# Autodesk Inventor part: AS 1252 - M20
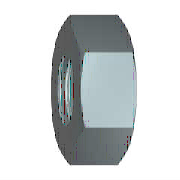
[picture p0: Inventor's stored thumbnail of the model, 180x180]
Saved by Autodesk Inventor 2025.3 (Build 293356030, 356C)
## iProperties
IsCustomPart: 0
Created: 2024-01
Part Number: AS 1252 - M20
Material: Acero, suave
Description: Pernos de acero Perno hex
Document SubType Name: Modeling
Standard: AS 1252
Designer: User
Standards Organization: AS
Language: es-ES
Size Designation: M20
Categories: <MemberInstance><Categories><Category DisplayName="Fijaciones" InternalName="e4da775c-781d-43d5-af7c-5136215cf5a6" Mnemonic="FSTN"><Category DisplayName="Tuerca
Density: 7.85 g/cm^3
Appearance: Semipulido
Author: User
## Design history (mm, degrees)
workaxis "Work Axis1"
workplane "Work Plane1"
sketch "Boceto1"
  geometry: L1 (-18.475, 0)-(-9.238, 16); L2 (-9.238, 16)-(9.238, 16); L3 (9.238, 16)-(18.475, 0); L4 (18.475, 0)-(9.238, -16); L5 (9.238, -16)-(-9.238, -16); L6 (-9.238, -16)-(-18.475, 0); 2 further points
  constraints: 12 end point, 1 coincident, 1 horizontal, 11 other
  dimensions: "d0" = 36.95042 distance of L3.end L1.start (= 1.1547 x SW)
extrude "Cuerpo" new body sketch "Boceto1" distance "d1" = 21.3 (= KOH); taper "d2" = 0 deg
revolve "Chaflán1" stored, may be unused: angle "d7" = 90 deg
sketch "Boceto3"
  geometry: A1 r 16 centre (0, 0) between (-8, -13.856) and (8, -13.856) reference; 1 further point
  constraints: 1 coincident
hole "Rosca" sketch "Boceto3" diameter "d25" = 17.294; stored, may be unused: countersink angle "d29" = 82 deg, drill point angle "d31" = 118 deg; dims "d26" = 6, "d27" = 4, "d28" = 2, "d30" = 8
body "Solid1"
chamfer "Chaflán2" distance "d8" = 1.35316 (= -0.5 x GD1 + 0.5 x NND); stored, may be unused: angle "d9" = 30 deg, second distance "d40" = 1.35316 (= -0.5 x GD1 + 0.5 x NND)
chamfer "Chaflán3" distance "d10" = 1.35316 (= -0.5 x GD1 + 0.5 x NND); stored, may be unused: angle "d11" = 30 deg, second distance "d41" = 1.35316 (= -0.5 x GD1 + 0.5 x NND)
sketch "Boceto2"
  geometry: L1 (0, 9.238)-(0, 18.475) reference; L2 (0, 18.475)-(21.3, 18.475) reference; L3 (21.3, 9.238)-(21.3, 18.475) reference; L4 (-4.26, 0)-(25.56, 0) reference; L5 (1.429, 18.475)-(0, 16); L6 (19.871, 18.475)-(21.3, 16)
  constraints: 4 end point, 4 point on line
  dimensions: "d3" = 30 deg angle of L1 L5 (= ANG1); "d4" = 30 deg angle of L3 L6 (= ANG2); "d5" = 32 diameter of L5.end L4 (= SW0); "d6" = 32 diameter of L6.end L4 (= SW01)
other parameters: "ANG1" = 30 deg [user parameter; used in 1 equation term], "ANG2" = 30 deg [user parameter; used in 1 equation term], "KOH" = 21.3 [user parameter; used in 1 equation term], "SW" = 32 [user parameter; used in 4 equation terms], "SW0" = 32 (= SW) [user parameter; used in 1 equation term], "SW01" = 32 (= SW) [user parameter; used in 1 equation term], "GD1" = 17.29367 (computed from THREADDIA, PTC, TOA) [user parameter; used in 4 equation terms], "d13" = 0, "d14" = 0, "d39" = 0, "d42" = 0, "GUL" = 1.35317 (= 0.541266 x PTC) [user parameter], "TPU" = 4 (computed from PTC) [user parameter], "WFT" = 0.8 [user parameter], "TOA" = 30 deg [user parameter; used in 1 equation term], "PTC" = 2.5 [user parameter; used in 4 equation terms], "E0" = 36.96 (= 1.155 x SW) [user parameter], "GAL" = 1.35317 (= 0.541266 x PTC) [user parameter]
